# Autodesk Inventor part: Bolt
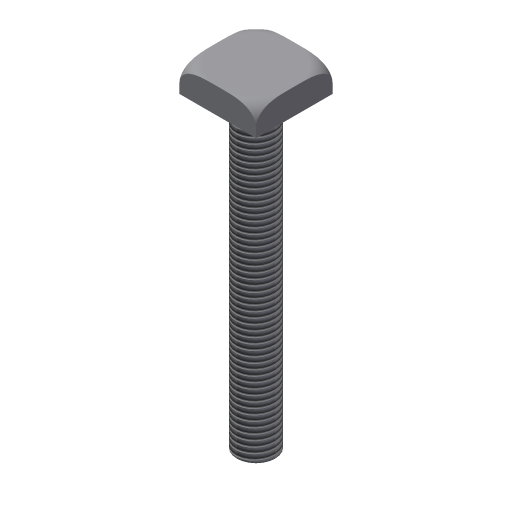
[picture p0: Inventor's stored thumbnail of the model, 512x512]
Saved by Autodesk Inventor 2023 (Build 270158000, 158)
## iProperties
Created: 2009-04
Part Number: Bolt
Document SubType Name: Modeling
Designer: Sham
Density: 1 g/cm^3
Material: Generic
Appearance: Default
Author: Sham
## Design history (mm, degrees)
sketch "Sketch1"
  geometry: L1 (-12, 12)-(12, 12); L2 (12, 12)-(12, -12); L3 (12, -12)-(-12, -12); L4 (-12, -12)-(-12, 12); 1 further point
  constraints: 8 end point, 2 parallel, 2 perpendicular, 1 horizontal, 1 other
  dimensions: "d0" = 24 distance of L1.start L1.end; "d1" = 12 distance from line of L2 point (0, 0); "d2" = 12 distance from line of L1 point (0, 0)
extrude "Extrusion1" new body sketch "Sketch1" distance "d3" = 8; taper "d4" = 0 deg
sketch "Sketch2"
  geometry: C1 r 6 at (0, 0)
  constraints: 1 centre point
  dimensions: "d5" = 12 diameter of C1
extrude "Extrusion2" join sketch "Sketch2" distance "d6" = 96; taper "d7" = 0 deg
workpoint "Work Point1"
workplane "Work Plane1"
sketch "Sketch3"
  geometry: L1 (33.941, 5)-(33.941, 6); L2 (28.941, 0)-(28.405, 0); L3 (16.971, 125.007)-(16.971, -22.043) reference; A1 r 5 centre (28.941, 5) between (28.941, 0) and (33.941, 5); 1 further point
  constraints: 4 end point, 2 point on circle, 2 point on line, 2 tangent, 1 centre point, 1 perpendicular
  dimensions: "d10" = 5 radius of A1
revolve "Revolution1" sketch "Sketch3" stored, may be unused: angle "d12" = 90 deg
thread "Thread1" dims "d13" = 96, "d14" = 0
body "Solid1"
other parameters: "d11" = 90 deg
